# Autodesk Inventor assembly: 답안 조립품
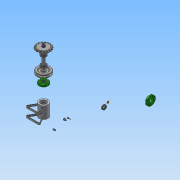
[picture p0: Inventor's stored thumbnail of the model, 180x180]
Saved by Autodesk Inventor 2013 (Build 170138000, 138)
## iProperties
Created: 2016-03
Part Number: 답안 조립품
Document SubType Name: Assembly
Designer: Administrator
Author: Administrator
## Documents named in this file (16)
- C:\Users\Administrator\Desktop\460308V1024\답안 조립품.iam
- C:\Users\Administrator\Desktop\460308V1024\본체.ipt
- C:\Users\Administrator\Desktop\460308V1024\V벨트풀리.ipt
- C:\Users\Administrator\Desktop\460308V1024\너트 M 8.ipt
- C:\Users\Administrator\Desktop\460308V1024\니플 M 6 x 0.75.ipt
- C:\Users\Administrator\Desktop\460308V1024\베어링 15 x 32 x 9.ipt
- C:\Users\Administrator\Desktop\460308V1024\볼트 M 6 x 8.ipt
- C:\Users\Administrator\Desktop\460308V1024\볼트 M4 x 12.ipt
- C:\Users\Administrator\Desktop\460308V1024\스프로킷.ipt
- C:\Users\Administrator\Desktop\460308V1024\스프링와셔 8.ipt
- C:\Users\Administrator\Desktop\460308V1024\오일 실 15 25 7.ipt
- C:\Users\Administrator\Desktop\460308V1024\와셔 6x11.5.ipt
- C:\Users\Administrator\Desktop\460308V1024\와셔 8x17.ipt
- C:\Users\Administrator\Desktop\460308V1024\축.ipt
- C:\Users\Administrator\Desktop\460308V1024\커버.ipt
- C:\Users\Administrator\Desktop\460308V1024\키 3 x 3 x 12.ipt
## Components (4 placed, 3 different names)
1. V벨트풀리:1
2. KS B 2023 6002 - 15 x 32 x 9:1
3. ISO 4762 M4 x 12:1
4. KS B 2023 6002 - 15 x 32 x 9:2
